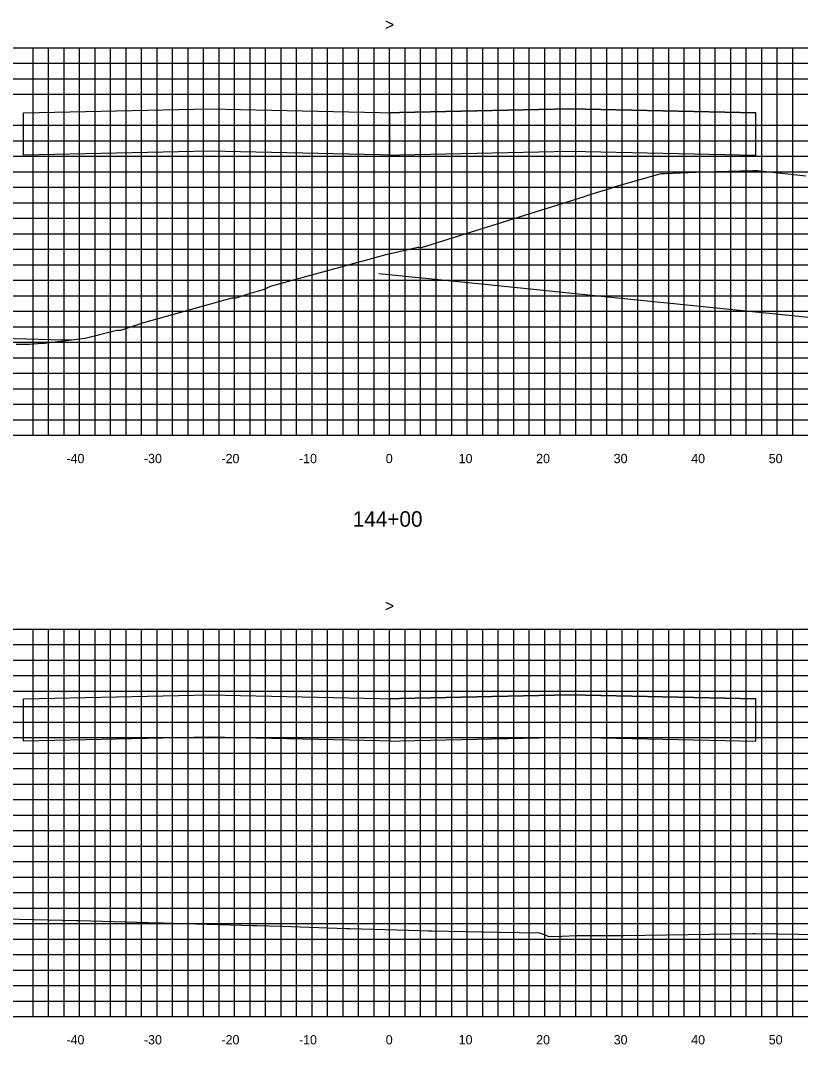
# Model space of a CAD drawing. Extents: x 1800880 to 1818864, y 245271 to 250560.
# Drawn here: x 1809383.4 to 1809484, y 250095.8 to 250228 of the extents above; entities that cross this region are included whole.
import ezdxf

# ---------------------------------------------------------------- set-up
doc = ezdxf.new("R2010")
doc.units = 0
for name, color, linetype in [('CL-CNST', 7, 'Continuous'), ('DESIGN - DRAINAGE - Bridges', 7, 'Continuous'), ('Level 32', 7, 'Continuous'), ('Level 46', 7, 'Continuous'), ('Level 62', 7, 'Continuous'), ('TOPO', 7, 'Continuous')]:
    doc.layers.add(name, color=color, linetype=linetype)

msp = doc.modelspace()

# ---------------------------------------------------------------- linework, layer by layer
at = {"layer": 'CL-CNST'}
for points in [[(1809382.81, 250186.18), (1809384.54, 250186.19), (1809386.16, 250186.32), (1809386.45, 250186.32), (1809391.71, 250186.96), (1809395.81, 250188.01), (1809395.95, 250188.01), (1809396.34, 250188), (1809399.3, 250188.97), (1809410.68, 250192.17), (1809410.75, 250192.17), (1809411.19, 250192.15), (1809413.05, 250192.77), (1809414.86, 250193.3), (1809415.62, 250193.67), (1809430.57, 250197.74), (1809434.63, 250198.71), (1809434.77, 250198.7), (1809435.12, 250198.68), (1809456.15, 250205.26), (1809456.42, 250205.39), (1809459.42, 250206.29), (1809460.26, 250206.57), (1809466.04, 250208.2), (1809466.52, 250208.2), (1809470.56, 250208.4), (1809471.47, 250208.43), (1809477.85, 250208.61), (1809477.91, 250208.61), (1809478.16, 250208.61), (1809478.4, 250208.61), (1809483.16, 250208.09), (1809484.69, 250207.92)], [(1809381.31, 250112.05), (1809387.07, 250111.89), (1809390.51, 250111.8), (1809390.97, 250111.8), (1809401.32, 250111.52), (1809401.36, 250111.52), (1809401.8, 250111.52), (1809403.08, 250111.49), (1809413.37, 250111.19), (1809413.48, 250111.19), (1809413.85, 250111.19), (1809417.12, 250111.1), (1809425.39, 250110.77), (1809425.61, 250110.77), (1809425.88, 250110.77), (1809434.93, 250110.51), (1809435.95, 250110.48), (1809436.43, 250110.48), (1809445.14, 250110.3), (1809450.35, 250110.24), (1809450.94, 250110), (1809451.52, 250109.75), (1809453.2, 250109.78), (1809455.15, 250109.87), (1809455.2, 250109.89), (1809459.84, 250109.88), (1809459.99, 250109.88), (1809461.17, 250109.89), (1809477.87, 250110.12), (1809478.15, 250110.12), (1809486.5, 250110.02)]]:
    msp.add_lwpolyline(points, dxfattribs=at)
at = {"layer": 'DESIGN - DRAINAGE - Bridges'}
for p, q in [((1809281, 250174.43), (1809581, 250174.43)), ((1809391, 250174.37), (1809391, 250174.43)), ((1809401, 250174.37), (1809401, 250174.43)), ((1809411, 250174.37), (1809411, 250174.43)), ((1809421, 250174.37), (1809421, 250174.43)), ((1809431, 250174.37), (1809431, 250174.43)), ((1809441, 250174.37), (1809441, 250174.43)), ((1809451, 250174.37), (1809451, 250174.43)), ((1809461, 250174.37), (1809461, 250174.43)), ((1809471, 250174.37), (1809471, 250174.43)), ((1809481, 250174.37), (1809481, 250174.43)), ((1809281, 250099.43), (1809581, 250099.43)), ((1809391, 250099.37), (1809391, 250099.43)), ((1809401, 250099.37), (1809401, 250099.43)), ((1809411, 250099.37), (1809411, 250099.43)), ((1809421, 250099.37), (1809421, 250099.43)), ((1809431, 250099.37), (1809431, 250099.43)), ((1809441, 250099.37), (1809441, 250099.43)), ((1809451, 250099.37), (1809451, 250099.43)), ((1809461, 250099.37), (1809461, 250099.43)), ((1809471, 250099.37), (1809471, 250099.43)), ((1809481, 250099.37), (1809481, 250099.43))]:
    msp.add_line(p, q, dxfattribs=at)
at = {"layer": 'Level 46'}
for p, q in [((1809281, 250224.43), (1809581, 250224.43)), ((1809385, 250174.43), (1809385, 250224.43)), ((1809387, 250174.43), (1809387, 250224.43)), ((1809389, 250174.43), (1809389, 250224.43)), ((1809391, 250174.43), (1809391, 250224.43)), ((1809393, 250174.43), (1809393, 250224.43)), ((1809395, 250174.43), (1809395, 250224.43)), ((1809397, 250174.43), (1809397, 250224.43)), ((1809399, 250174.43), (1809399, 250224.43)), ((1809401, 250174.43), (1809401, 250224.43)), ((1809403, 250174.43), (1809403, 250224.43)), ((1809405, 250174.43), (1809405, 250224.43)), ((1809407, 250174.43), (1809407, 250224.43)), ((1809409, 250174.43), (1809409, 250224.43)), ((1809411, 250174.43), (1809411, 250224.43)), ((1809413, 250174.43), (1809413, 250224.43)), ((1809415, 250174.43), (1809415, 250224.43)), ((1809417, 250174.43), (1809417, 250224.43)), ((1809419, 250174.43), (1809419, 250224.43)), ((1809421, 250174.43), (1809421, 250224.43)), ((1809423, 250174.43), (1809423, 250224.43)), ((1809425, 250174.43), (1809425, 250224.43)), ((1809427, 250174.43), (1809427, 250224.43)), ((1809429, 250174.43), (1809429, 250224.43)), ((1809431, 250174.43), (1809431, 250224.43)), ((1809433, 250174.43), (1809433, 250224.43)), ((1809435, 250174.43), (1809435, 250224.43)), ((1809437, 250174.43), (1809437, 250224.43)), ((1809439, 250174.43), (1809439, 250224.43)), ((1809441, 250174.43), (1809441, 250224.43)), ((1809443, 250174.43), (1809443, 250224.43)), ((1809445, 250174.43), (1809445, 250224.43)), ((1809447, 250174.43), (1809447, 250224.43)), ((1809449, 250174.43), (1809449, 250224.43)), ((1809451, 250174.43), (1809451, 250224.43)), ((1809453, 250174.43), (1809453, 250224.43)), ((1809455, 250174.43), (1809455, 250224.43)), ((1809457, 250174.43), (1809457, 250224.43)), ((1809459, 250174.43), (1809459, 250224.43)), ((1809461, 250174.43), (1809461, 250224.43)), ((1809463, 250174.43), (1809463, 250224.43)), ((1809465, 250174.43), (1809465, 250224.43)), ((1809467, 250174.43), (1809467, 250224.43)), ((1809469, 250174.43), (1809469, 250224.43)), ((1809471, 250174.43), (1809471, 250224.43)), ((1809473, 250174.43), (1809473, 250224.43)), ((1809475, 250174.43), (1809475, 250224.43)), ((1809477, 250174.43), (1809477, 250224.43)), ((1809479, 250174.43), (1809479, 250224.43)), ((1809481, 250174.43), (1809481, 250224.43)), ((1809483, 250174.43), (1809483, 250224.43)), ((1809281, 250222.43), (1809581, 250222.43)), ((1809281, 250220.43), (1809581, 250220.43)), ((1809281, 250218.43), (1809581, 250218.43)), ((1809281, 250214.43), (1809581, 250214.43)), ((1809281, 250212.43), (1809581, 250212.43)), ((1809281, 250210.43), (1809581, 250210.43)), ((1809281, 250208.43), (1809581, 250208.43)), ((1809281, 250206.43), (1809581, 250206.43)), ((1809281, 250204.43), (1809581, 250204.43)), ((1809281, 250202.43), (1809581, 250202.43)), ((1809281, 250200.43), (1809581, 250200.43)), ((1809281, 250198.43), (1809581, 250198.43)), ((1809281, 250196.43), (1809581, 250196.43)), ((1809281, 250194.43), (1809581, 250194.43)), ((1809281, 250192.43), (1809581, 250192.43)), ((1809281, 250190.43), (1809581, 250190.43)), ((1809281, 250188.43), (1809581, 250188.43)), ((1809281, 250186.43), (1809581, 250186.43)), ((1809281, 250184.43), (1809581, 250184.43)), ((1809281, 250182.43), (1809581, 250182.43)), ((1809281, 250180.43), (1809581, 250180.43)), ((1809281, 250178.43), (1809581, 250178.43)), ((1809281, 250176.43), (1809581, 250176.43)), ((1809281, 250174.43), (1809581, 250174.43)), ((1809281, 250149.43), (1809581, 250149.43)), ((1809385, 250099.43), (1809385, 250149.43)), ((1809387, 250099.43), (1809387, 250149.43)), ((1809389, 250099.43), (1809389, 250149.43)), ((1809391, 250099.43), (1809391, 250149.43)), ((1809393, 250099.43), (1809393, 250149.43)), ((1809395, 250099.43), (1809395, 250149.43)), ((1809397, 250099.43), (1809397, 250149.43)), ((1809399, 250099.43), (1809399, 250149.43)), ((1809401, 250099.43), (1809401, 250149.43)), ((1809403, 250099.43), (1809403, 250149.43)), ((1809405, 250099.43), (1809405, 250149.43)), ((1809407, 250099.43), (1809407, 250149.43)), ((1809409, 250099.43), (1809409, 250149.43)), ((1809411, 250099.43), (1809411, 250149.43)), ((1809413, 250099.43), (1809413, 250149.43)), ((1809415, 250099.43), (1809415, 250149.43)), ((1809417, 250099.43), (1809417, 250149.43)), ((1809419, 250099.43), (1809419, 250149.43)), ((1809421, 250099.43), (1809421, 250149.43)), ((1809423, 250099.43), (1809423, 250149.43)), ((1809425, 250099.43), (1809425, 250149.43)), ((1809427, 250099.43), (1809427, 250149.43)), ((1809429, 250099.43), (1809429, 250149.43)), ((1809431, 250099.43), (1809431, 250149.43)), ((1809433, 250099.43), (1809433, 250149.43)), ((1809435, 250099.43), (1809435, 250149.43)), ((1809437, 250099.43), (1809437, 250149.43)), ((1809439, 250099.43), (1809439, 250149.43)), ((1809441, 250099.43), (1809441, 250149.43)), ((1809443, 250099.43), (1809443, 250149.43)), ((1809445, 250099.43), (1809445, 250149.43)), ((1809447, 250099.43), (1809447, 250149.43)), ((1809449, 250099.43), (1809449, 250149.43)), ((1809451, 250099.43), (1809451, 250149.43)), ((1809453, 250099.43), (1809453, 250149.43)), ((1809455, 250099.43), (1809455, 250149.43)), ((1809457, 250099.43), (1809457, 250149.43)), ((1809459, 250099.43), (1809459, 250149.43)), ((1809461, 250099.43), (1809461, 250149.43)), ((1809463, 250099.43), (1809463, 250149.43)), ((1809465, 250099.43), (1809465, 250149.43)), ((1809467, 250099.43), (1809467, 250149.43)), ((1809469, 250099.43), (1809469, 250149.43)), ((1809471, 250099.43), (1809471, 250149.43)), ((1809473, 250099.43), (1809473, 250149.43)), ((1809475, 250099.43), (1809475, 250149.43)), ((1809477, 250099.43), (1809477, 250149.43)), ((1809479, 250099.43), (1809479, 250149.43)), ((1809481, 250099.43), (1809481, 250149.43)), ((1809483, 250099.43), (1809483, 250149.43)), ((1809281, 250147.43), (1809581, 250147.43)), ((1809281, 250145.43), (1809581, 250145.43)), ((1809281, 250143.43), (1809581, 250143.43)), ((1809281, 250141.43), (1809581, 250141.43)), ((1809281, 250139.43), (1809581, 250139.43)), ((1809281, 250137.43), (1809581, 250137.43)), ((1809281, 250135.43), (1809581, 250135.43)), ((1809281, 250133.43), (1809581, 250133.43)), ((1809281, 250131.43), (1809581, 250131.43)), ((1809281, 250129.43), (1809581, 250129.43)), ((1809281, 250127.43), (1809581, 250127.43)), ((1809281, 250125.43), (1809581, 250125.43)), ((1809281, 250123.43), (1809581, 250123.43)), ((1809281, 250121.43), (1809581, 250121.43)), ((1809281, 250119.43), (1809581, 250119.43)), ((1809281, 250117.43), (1809581, 250117.43)), ((1809281, 250115.43), (1809581, 250115.43)), ((1809281, 250113.43), (1809581, 250113.43)), ((1809281, 250111.43), (1809581, 250111.43)), ((1809281, 250109.43), (1809581, 250109.43)), ((1809281, 250107.43), (1809581, 250107.43)), ((1809281, 250105.43), (1809581, 250105.43)), ((1809281, 250103.43), (1809581, 250103.43)), ((1809281, 250101.43), (1809581, 250101.43)), ((1809281, 250099.43), (1809581, 250099.43))]:
    msp.add_line(p, q, dxfattribs=at)
at = {"layer": 'Level 62'}
for points in [[(1809383.75, 250216.02), (1809395.75, 250216.28), (1809407.75, 250216.55), (1809419.75, 250216.28), (1809429.75, 250216.06), (1809431, 250216.03), (1809431, 250216.03), (1809432.25, 250216.06), (1809442.25, 250216.28), (1809454.25, 250216.55), (1809466.25, 250216.28), (1809478.25, 250216.02)], [(1809429.6, 250195.3), (1809443.71, 250193.87), (1809457.04, 250192.51), (1809507.95, 250187.34), (1809508.29, 250187.34), (1809512.02, 250187.33), (1809513.06, 250187.5), (1809526.91, 250189.72), (1809533.3, 250190.76), (1809533.41, 250190.76), (1809535.31, 250190.83), (1809535.6, 250190.84), (1809539.33, 250190.91), (1809544.69, 250190.78), (1809563.43, 250190.3), (1809568.43, 250190.09), (1809571.46, 250189.96), (1809572.92, 250189.89), (1809573.47, 250189.87), (1809579.86, 250188.79), (1809581, 250188.59)], [(1809281, 250186.85), (1809308.05, 250187.14), (1809333.53, 250186.97), (1809335.81, 250186.98), (1809361.25, 250187.42), (1809363.56, 250187.43), (1809388.88, 250186.74), (1809389.98, 250186.75)], [(1809383.75, 250140.42), (1809395.75, 250140.68), (1809407.75, 250140.94), (1809419.75, 250140.68), (1809429.75, 250140.46), (1809431, 250140.43), (1809431, 250140.43), (1809432.25, 250140.46), (1809442.25, 250140.68), (1809454.25, 250140.94), (1809466.25, 250140.68), (1809478.25, 250140.42)]]:
    msp.add_lwpolyline(points, dxfattribs=at)
at = {"layer": 'TOPO'}
for points in [[(1809395.75, 250210.82), (1809383.75, 250210.56), (1809383.75, 250216.02), (1809395.75, 250216.28), (1809407.75, 250216.55), (1809419.75, 250216.28), (1809429.75, 250216.06), (1809431, 250216.03), (1809431, 250210.57), (1809429.75, 250210.6), (1809419.75, 250210.82), (1809407.75, 250211.09)], [(1809466.25, 250210.82), (1809478.25, 250210.56), (1809478.25, 250216.02), (1809466.25, 250216.28), (1809454.25, 250216.55), (1809442.25, 250216.28), (1809432.25, 250216.06), (1809431, 250216.03), (1809431, 250210.57), (1809432.25, 250210.6), (1809442.25, 250210.82), (1809454.25, 250211.09)], [(1809395.75, 250135.22), (1809383.75, 250134.96), (1809383.75, 250140.42), (1809395.75, 250140.68), (1809407.75, 250140.94), (1809419.75, 250140.68), (1809429.75, 250140.46), (1809431, 250140.43), (1809431, 250134.97), (1809429.75, 250135), (1809419.75, 250135.22), (1809407.75, 250135.48)], [(1809466.25, 250135.22), (1809478.25, 250134.96), (1809478.25, 250140.42), (1809466.25, 250140.68), (1809454.25, 250140.94), (1809442.25, 250140.68), (1809432.25, 250140.46), (1809431, 250140.43), (1809431, 250134.97), (1809432.25, 250135), (1809442.25, 250135.22), (1809454.25, 250135.48)]]:
    msp.add_lwpolyline(points, close=True, dxfattribs=at)

# ---------------------------------------------------------------- texts
for s, p in [('-40', (1809389.3, 250170.83)), ('-30', (1809399.3, 250170.83)), ('-20', (1809409.3, 250170.83)), ('-10', (1809419.3, 250170.83)), ('0', (1809430.5, 250170.83)), ('10', (1809439.9, 250170.83)), ('20', (1809449.9, 250170.83)), ('30', (1809459.9, 250170.83)), ('40', (1809469.9, 250170.83)), ('50', (1809479.9, 250170.83)), ('-40', (1809389.3, 250095.83)), ('-30', (1809399.3, 250095.83)), ('-20', (1809409.3, 250095.83)), ('-10', (1809419.3, 250095.83)), ('0', (1809430.5, 250095.83)), ('10', (1809439.9, 250095.83)), ('20', (1809449.9, 250095.83)), ('30', (1809459.9, 250095.83)), ('40', (1809469.9, 250095.83)), ('50', (1809479.9, 250095.83))]:
    msp.add_text(s, height=1.2).set_placement(p)
at = {"layer": 'DESIGN - DRAINAGE - Bridges'}
for p in [(1809430.39, 250226.68), (1809430.39, 250151.68)]:
    msp.add_text('>', height=1.5, dxfattribs=at).set_placement(p)
at = {"layer": 'Level 32'}
msp.add_text('144+00', height=2, dxfattribs=at).set_placement((1809426.24, 250162.63))

doc.saveas('drawing.dxf')
